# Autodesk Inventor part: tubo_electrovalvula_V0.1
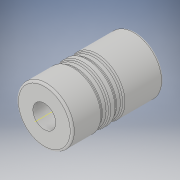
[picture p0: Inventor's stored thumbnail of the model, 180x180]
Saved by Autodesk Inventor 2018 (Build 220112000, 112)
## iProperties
Created: 2018-09
Part Number: tubo_electrovalvula_V0.1
Material: Generic
Document SubType Name: Modeling
Designer: Gordillo
Density: 1 g/cm^3
Appearance: Default
Author: Gordillo
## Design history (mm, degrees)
sketch "Sketch1"
  geometry: C1 r 55 at (0, 0); 1 further point
  constraints: 1 centre point, 1 coincident
  dimensions: "d0" = 110 diameter of C1
extrude "Extrusion1" new body sketch "Sketch1" distance "d1" = 180; taper "d2" = 0 deg
sketch "Sketch2"
  geometry: L1 (55, 180)-(-55, 180) reference; L2 (-55, 0)-(55, 0) reference; L3 (55, 0)-(55, 180) reference; L4 (55, 80)-(52, 80); L5 (52, 80)-(52, 92); L6 (52, 92)-(55, 92); L7 (55, 92)-(55, 80); L8 (55, 108)-(52, 108); L9 (52, 108)-(52, 120); L10 (52, 120)-(55, 120); L11 (55, 120)-(55, 108); L12 (0, -36)-(0, 216) reference; 1 further point
  constraints: 16 end point, 4 parallel, 2 horizontal, 2 perpendicular, 2 point on line
  dimensions: "d3" = 3 distance of L5.end L6.end; "d4" = 12 distance of L4.end L5.end; "d5" = 80 distance between parallel lines of L2 L4; "d6" = 3 distance of L9.end L10.end; "d7" = 12 distance of L8.end L9.end; "d8" = 16 distance between parallel lines of L8 L6
revolve "Revolution1" sketch "Sketch2" stored, may be unused: angle "d9" = 90 deg
fillet "Fillet1" dims "d10" = 4
sketch "Sketch3"
  geometry: C1 r 22.5 at (0, 0); 1 further point
  constraints: 1 centre point, 1 coincident
  dimensions: "d11" = 45 diameter of C1
extrude "Extrusion2" cut sketch "Sketch3" distance "d12" = 150; taper "d13" = 0 deg
fillet "Fillet2" dims "d14" = 4
workplane "Work Plane1"
sketch "Sketch4"
  geometry: L1 (0, -36)-(0, 216) reference; L2 (51, 0)-(-51, 0) reference; 2 further points
  constraints: 1 point on line
  dimensions: "d15" = 45 distance from line of L2 point (0, 45)
hole "Hole1" sketch "Sketch4" at (0, 45) diameter "d16" = 12; stored, may be unused: countersink angle "d20" = 90 deg, drill point angle "d22" = 118 deg; dims "d17" = 6, "d18" = 14, "d19" = 4, "d21" = 8
thread "Thread1" dims "d23" = 10, "d24" = 0
body "Solid1"
node "Projected Loop1"
